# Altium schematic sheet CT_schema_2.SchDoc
size 398 x 262 mm
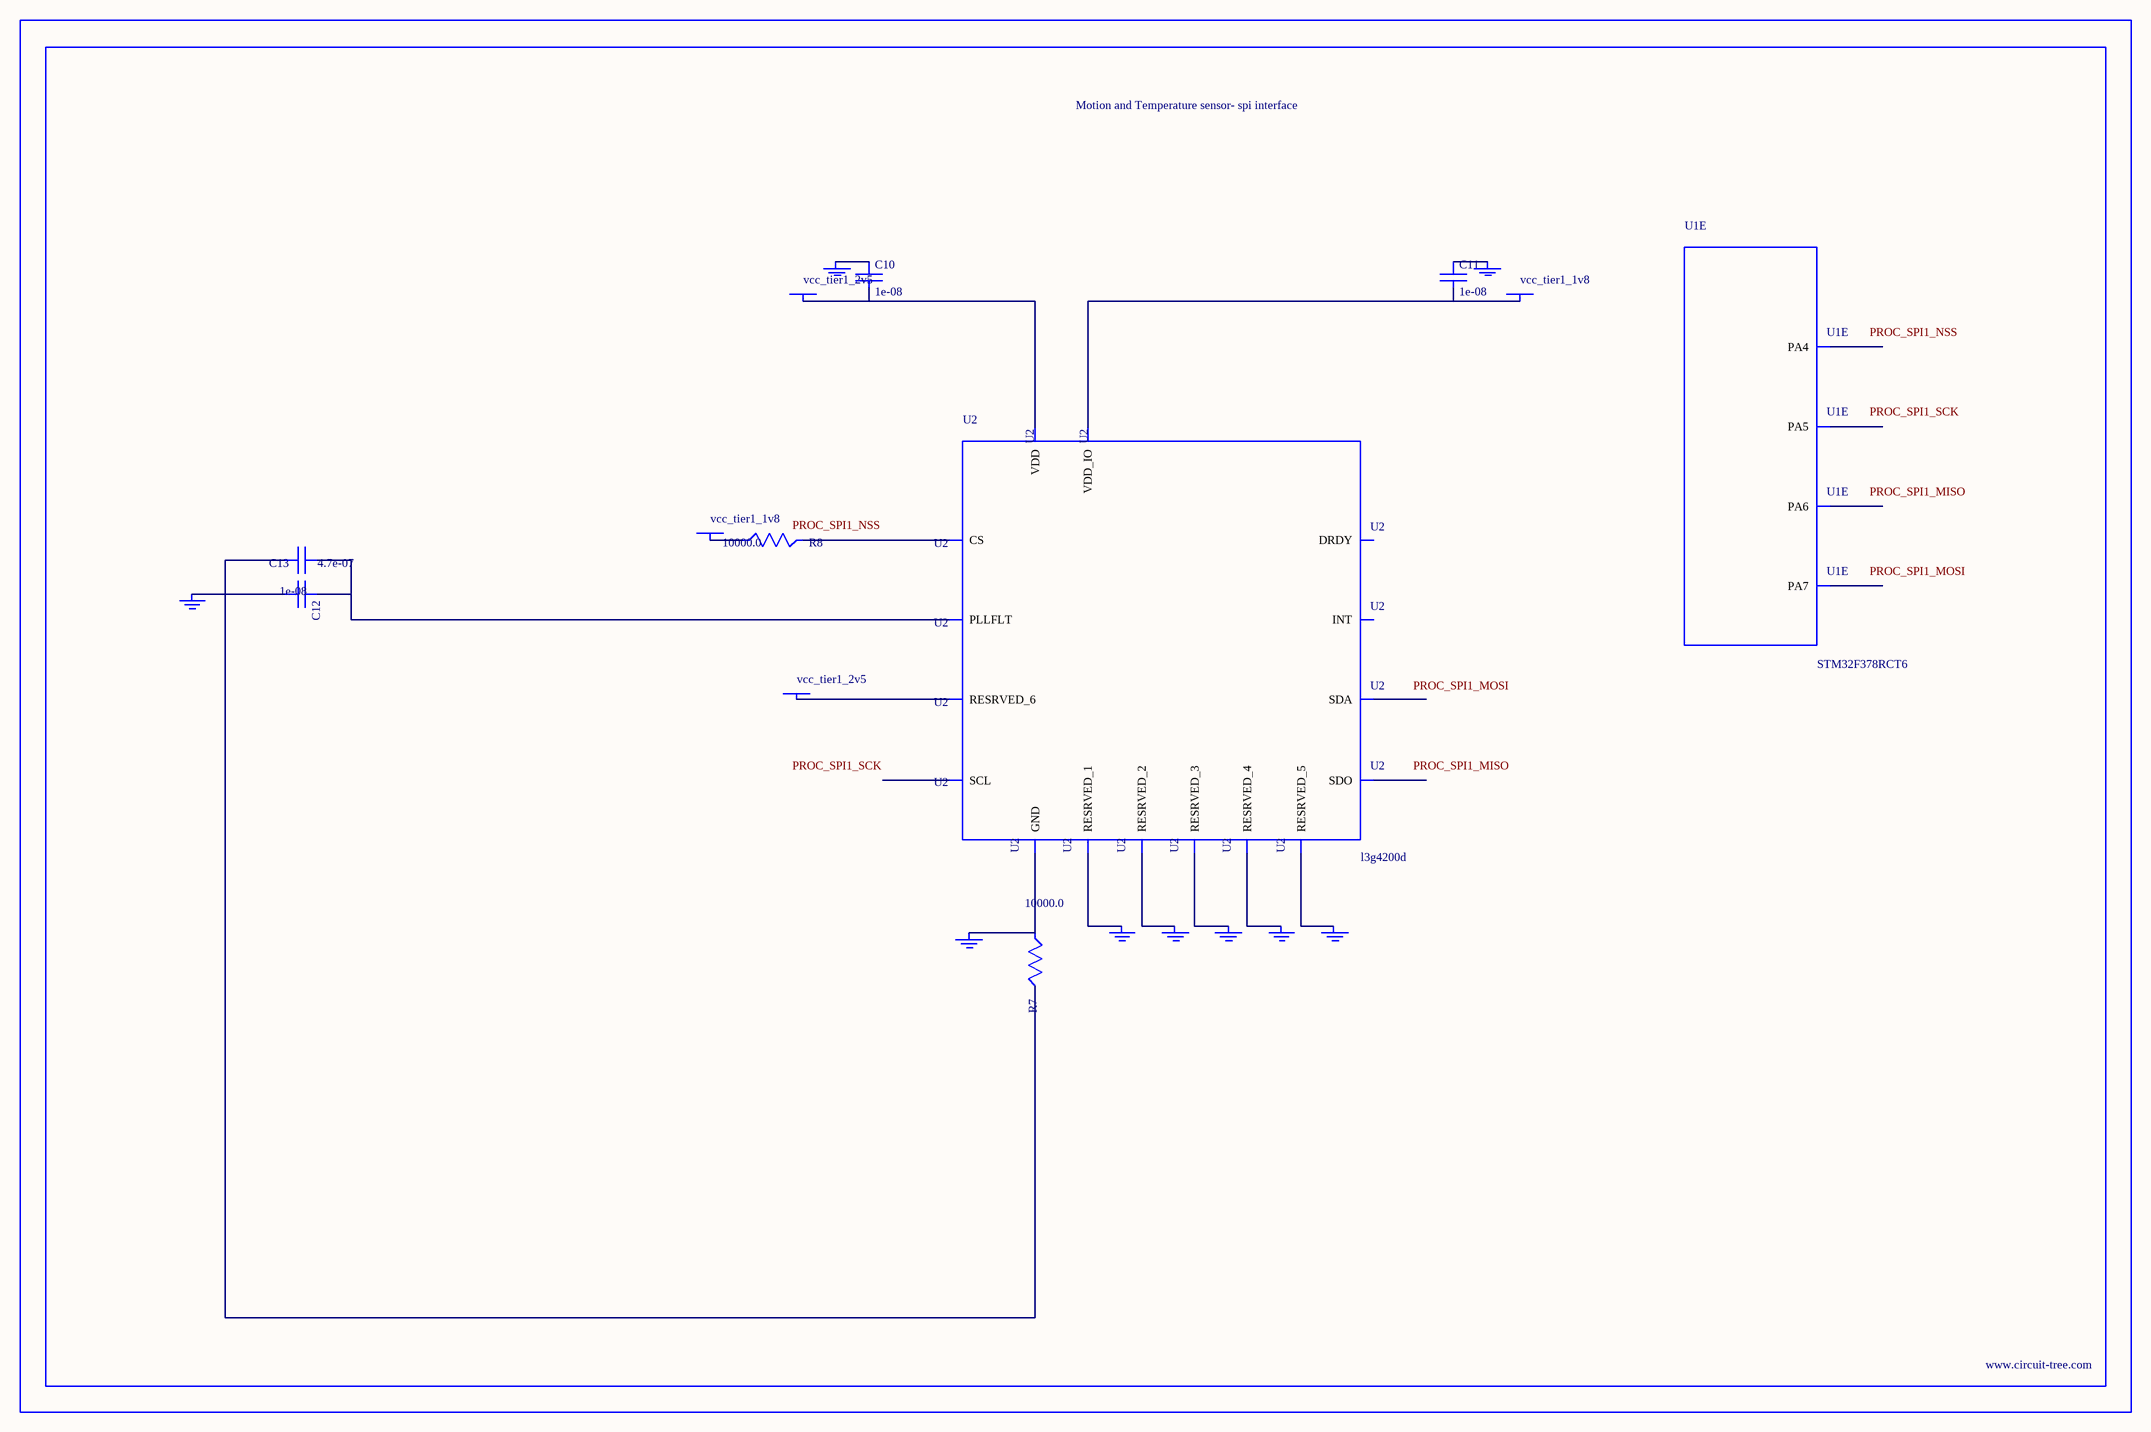
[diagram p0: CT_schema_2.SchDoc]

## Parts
BORDER1  (no value)
C10  1e-08  [C0402]
C11  1e-08  [C0402]
C12  1e-08  [C0402]
C13  4.7e-07  [C0603]
GND_INSTANCE_1_0  (no value)
GND_INSTANCE_1_1  (no value)
GND_INSTANCE_1_2  (no value)
GND_INSTANCE_1_3  (no value)
GND_INSTANCE_1_4  (no value)
GND_INSTANCE_1_5  (no value)
GND_INSTANCE_1_6  (no value)
GND_INSTANCE_1_7  (no value)
GND_INSTANCE_1_8  (no value)
POWER_INSTANCE_1_0  vcc_tier1_1v8
POWER_INSTANCE_1_1  vcc_tier1_1v8
POWER_INSTANCE_1_2  vcc_tier1_2v5
POWER_INSTANCE_1_3  vcc_tier1_2v5
R7  10000.0  [R0603]
R8  10000.0  [R0603]
U1  STM32F378RCT6  [LQFP64]  (part E of 6)
U2  l3g4200d  [LGA-16]

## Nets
NetC10_1: C10.1 GND_INSTANCE_1_8.0(GND)
NetC10_2: C10.2 POWER_INSTANCE_1_3.0(PWR) U2.16(VDD)
NetC11_1: C11.1 GND_INSTANCE_1_0.0(GND)
NetC11_2: C11.2 POWER_INSTANCE_1_0.0(PWR) U2.1(VDD_IO)
NetC12_1: C12.1 C13.1 U2.14(PLLFLT)
NetC12_2: C12.2 C13.2 GND_INSTANCE_1_7.0(GND) R7.2
NetGND_INSTANCE_1_1_0: GND_INSTANCE_1_1.0(GND) U2.8(RESRVED_1)
NetGND_INSTANCE_1_2_0: GND_INSTANCE_1_2.0(GND) U2.9(RESRVED_2)
NetGND_INSTANCE_1_3_0: GND_INSTANCE_1_3.0(GND) U2.10(RESRVED_3)
NetGND_INSTANCE_1_4_0: GND_INSTANCE_1_4.0(GND) U2.11(RESRVED_4)
NetGND_INSTANCE_1_5_0: GND_INSTANCE_1_5.0(GND) U2.12(RESRVED_5)
NetGND_INSTANCE_1_6_0: GND_INSTANCE_1_6.0(GND) R7.1 U2.13(GND)
NetPOWER_INSTANCE_1_1_0: POWER_INSTANCE_1_1.0(PWR) R8.1
NetPOWER_INSTANCE_1_2_0: POWER_INSTANCE_1_2.0(PWR) U2.15(RESRVED_6)
NetR8_2: R8.2 U2.5(CS)

Not connected (* = marked no-connect by the designer): U1 20(PA4) 21(PA5) 22(PA6) 23(PA7); U2 2(SCL) 3(SDA) 4(SDO) 6(DRDY) 7(INT)

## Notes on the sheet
- Labels drawn without touching a wire or pin: PROC_SPI1_MISO, PROC_SPI1_MOSI, PROC_SPI1_NSS, PROC_SPI1_SCK

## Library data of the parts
BORDER1 = BORDER_PAGE1
C10-C12 = C0402C103K3RAC
C13 = C0603C474K3RAC
GND_INSTANCE_1_0-GND_INSTANCE_1_8 = GND
POWER_INSTANCE_1_0-POWER_INSTANCE_1_3 = PWR
R7 R8 = RC0603JR-0710KL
